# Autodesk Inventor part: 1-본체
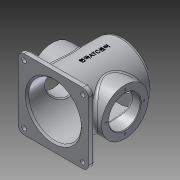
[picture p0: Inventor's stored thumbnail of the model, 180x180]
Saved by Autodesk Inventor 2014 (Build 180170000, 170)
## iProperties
Created: 2015-10
Part Number: 1-본체
Material: 알루미늄 6061
Document SubType Name: Modeling
Designer: Administrator
Density: 2.71 g/cm^3
Appearance: 알루미늄 - 평지
Mass: 984.531 g
Surface Area: 1041.03 cm^2
Volume: 363.296 cm^3
Author: Administrator
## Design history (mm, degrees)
sketch "스케치1"
  geometry: C1 r 50 at (0, 0); 1 further point
  constraints: 1 centre point, 1 coincident
  dimensions: "d0" = 100 diameter of C1
extrude "돌출1" new body sketch "스케치1" distance "d1" = 110; taper "d2" = 0 deg
sketch "스케치2"
  geometry: L1 (-60, 60)-(60, 60); L2 (60, 60)-(60, -60); L3 (60, -60)-(-60, -60); L4 (-60, -60)-(-60, 60); 3 further points
  constraints: 8 end point, 2 midpoint, 2 parallel, 2 perpendicular, 1 horizontal, 1 horizontal alignment, 1 vertical alignment
  dimensions: "d3" = 120 distance of L1.end L2.end
extrude "돌출2" join sketch "스케치2" distance "d4" = 10; taper "d5" = 0 deg
sketch "스케치3"
  geometry: C1 r 40 at (0, 0); 1 further point
  constraints: 1 centre point, 1 coincident
  dimensions: "d6" = 80 diameter of C1
extrude "돌출3" join sketch "스케치3" distance "d7" = 5; taper "d8" = 0 deg
sketch "스케치7"
  geometry: L1 (-10, -60)-(-10, 60) reference; C1 r 40 at (50, 0); 2 further points
  constraints: 1 centre point, 1 horizontal alignment, 1 midpoint
  dimensions: "d19" = 80 diameter of C1; "d20" = 60 distance from line of C1.centre L1
extrude "돌출7" join sketch "스케치7" stored distance "d21" = 124; taper "d22" = 0 deg
sketch "스케치8"
  geometry: C1 r 45 at (0, 0); 1 further point
  constraints: 1 centre point, 1 coincident
  dimensions: "d23" = 90 diameter of C1
extrude "돌출8" cut sketch "스케치8" distance "d24" = 112; taper "d25" = 0 deg
sketch "스케치9"
  geometry: C1 r 27 at (0, 0); 1 further point
  constraints: 1 centre point, 1 coincident
  dimensions: "d26" = 54 diameter of C1
extrude "돌출9" cut sketch "스케치9" distance "d27" = 13; taper "d28" = 0 deg
sketch "스케치10"
  geometry: C1 r 27 at (0, 0); C2 r 40 at (0, 0) reference; 1 further point
  constraints: 1 centre point, 1 concentric
  dimensions: "d29" = 54 diameter of C1
extrude "돌출10" cut sketch "스케치10" stored distance "d30" = 0; taper "d31" = 0 deg
fillet "모깎기1" dims "d32" = 5
fillet "모깎기2" dims "d33" = 5
fillet "모깎기3" dims "d34" = 10
fillet "모깎기4" dims "d35" = 3
chamfer "모따기1" distance "d36" = 3; stored, may be unused: second distance "d37" = 2, angle "d38" = 45 deg
chamfer "모따기2" distance "d39" = 1; stored, may be unused: second distance "d40" = 2, angle "d41" = 45 deg
chamfer "모따기3" distance "d42" = 1; stored, may be unused: second distance "d43" = 2, angle "d44" = 45 deg
chamfer "모따기4" distance "d45" = 1; stored, may be unused: second distance "d46" = 2, angle "d47" = 45 deg
sketch "스케치11"
  geometry: L1 (0, 0)-(22.981, 22.981); L2 (0, 0)-(0, 32.5); A1 r 32.5 centre (0, 0) between (22.981, 22.981) and (0, 32.5); 1 further point
  constraints: 4 end point, 2 point on circle, 1 centre point, 1 coincident, 1 vertical
  dimensions: "d49" = 65 diameter of A1; "d50" = 45 deg angle of L1 L2
hole "구멍1" sketch "스케치11" at (22.981, 22.981) diameter "d51" = 3.242; stored, may be unused: countersink angle "d55" = 90 deg, drill point angle "d57" = 118 deg; dims "d52" = 8, "d53" = 4, "d54" = 2, "d56" = 10
sketch "스케치12"
  geometry: L1 (0, 40)-(0, 0); L2 (0, 0)-(0, -32.5); C1 r 28 at (0, 0) reference; 2 further points
  constraints: 4 end point, 1 collinear, 1 vertical, 1 vertical alignment, 1 other
  dimensions: "d61" = 32.5 distance of L1.end L2.end
hole "구멍2" sketch "스케치12" at (0, -32.5) diameter "d62" = 3.242; stored, may be unused: countersink angle "d66" = 90 deg, drill point angle "d68" = 118 deg; dims "d63" = 8, "d64" = 4, "d65" = 2, "d67" = 10
sketch "스케치13"
  geometry: L1 (0, 28)-(0, 0); L2 (0, 0)-(0, -32.5); C1 r 40 at (0, 0) reference; 1 further point
  constraints: 4 end point, 1 collinear, 1 vertical, 1 vertical alignment, 1 other
  dimensions: "d72" = 32.5 distance of L1.end L2.end
hole "구멍3" sketch "스케치13" at (0, -32.5) diameter "d73" = 3.242; stored, may be unused: countersink angle "d77" = 90 deg, drill point angle "d79" = 118 deg; dims "d74" = 8, "d75" = 4, "d76" = 2, "d78" = 10
sketch "스케치14"
  geometry: L1 (-50, 50)-(50, 50); L2 (50, 50)-(50, -50); L3 (50, -50)-(-50, -50); L4 (-50, -50)-(-50, 50); 3 further points
  constraints: 8 end point, 2 midpoint, 2 parallel, 2 perpendicular, 1 horizontal, 1 horizontal alignment, 1 vertical alignment
  dimensions: "d83" = 100 distance of L1.start L1.end
hole "구멍4" sketch "스케치14" diameter "d84" = 8; stored, may be unused: countersink angle "d88" = 90 deg, drill point angle "d90" = 0 deg; dims "d85" = 8, "d86" = 4, "d87" = 2, "d89" = 10
node "작업 평면1"
sketch "스케치15"
  geometry: L1 (56.398, 35.113)-(56.398, 84.887); L2 (56.398, 84.887)-(63.602, 84.887); L3 (63.602, 84.887)-(63.602, 35.113); L4 (63.602, 35.113)-(56.398, 35.113); L5 (110, -10)-(10, -10) reference; 6 further points
  constraints: 4 midpoint, 2 vertical alignment, 2 other
  dimensions: "d97" = 70 distance from line of L5 point (63.602, 60)
feature "엠보싱1" sketch "스케치15" dims "d1" = 110, "d98" = 0.5, "d99" = 0
node "솔리드1"
pattern_circular "원형 패턴1" dims angle "d59" = 360 deg
pattern_circular "원형 패턴2" dims angle "d70" = 360 deg
pattern_circular "원형 패턴3" dims angle "d81" = 360 deg
pattern_linear "직사각형 패턴1" dims "d93" = 100 (= d83)
node "투영된 루프1"
node "투영된 루프2"
